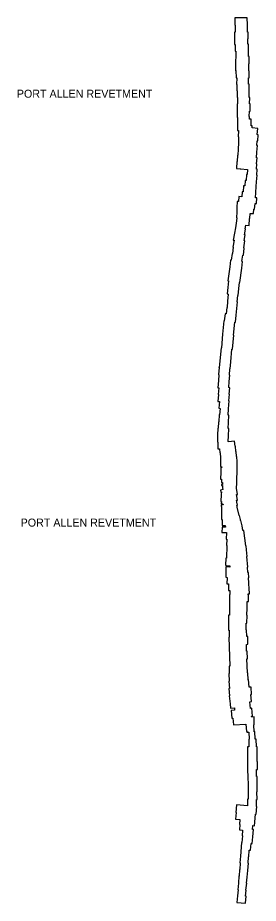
# Model space of a CAD drawing. Extents: x 2650582 to 3923188, y 277893 to 989177.
# Drawn here: x 3318306 to 3323118, y 703862 to 721562 of the extents above; entities that cross this region are included whole.
import ezdxf

# ---------------------------------------------------------------- set-up
doc = ezdxf.new("R2010")
doc.units = 0
doc.layers.add('Level 3', color=7, linetype='Continuous')

msp = doc.modelspace()

# ---------------------------------------------------------------- linework, layer by layer
at = {"layer": 'Level 3'}
for points in [[(3322897, 721562), (3322648, 721559), (3322650, 721411), (3322654, 721411), (3322653, 721273), (3322644, 721273), (3322644, 721170)], [(3322907, 721142), (3322916, 721141), (3322917, 721271), (3322901, 721271), (3322902, 721421), (3322899, 721421), (3322897, 721562)], [(3322644, 721170), (3322643, 721170), (3322643, 721027), (3322654, 721027), (3322655, 720895), (3322671, 720894), (3322672, 720789), (3322667, 720790), (3322665, 720691), (3322664, 720647), (3322663, 720647), (3322663, 720503), (3322672, 720504), (3322674, 720363), (3322686, 720363), (3322685, 720230), (3322692, 720230)], [(3322938, 720237), (3322923, 720237), (3322924, 720363), (3322937, 720363), (3322936, 720501), (3322932, 720501), (3322932, 720639), (3322935, 720639), (3322937, 720784), (3322923, 720784), (3322923, 720904), (3322920, 720904), (3322920, 721033), (3322906, 721033), (3322907, 721142)], [(3322692, 720230), (3322691, 720100), (3322696, 720100), (3322696, 719970), (3322700, 719970), (3322699, 719840), (3322693, 719840), (3322693, 719698), (3322696, 719698), (3322695, 719567), (3322699, 719567), (3322699, 719438), (3322700, 719438), (3322703, 719305), (3322719, 719305), (3322718, 719181), (3322724, 719181), (3322721, 719060), (3322713, 718938), (3322718, 718938), (3322709, 718817), (3322704, 718817), (3322695, 718688), (3322691, 718688), (3322681, 718545), (3322753, 718540), (3322753, 718539), (3322770, 718539), (3322895, 718530)], [(3322993, 719358), (3322995, 719400), (3322974, 719401), (3322978, 719532), (3322943, 719533), (3322943, 719587), (3322938, 719587), (3322939, 719697), (3322958, 719697), (3322958, 719840), (3322945, 719840), (3322946, 719970), (3322938, 719970), (3322938, 720101), (3322936, 720101), (3322938, 720237)], [(3322954, 717651), (3323024, 717646), (3323031, 717736), (3323045, 717735), (3323053, 717849), (3323079, 717847), (3323087, 717963), (3323063, 717964), (3323070, 718066), (3323069, 718066), (3323077, 718187), (3323073, 718188), (3323080, 718283), (3323084, 718283), (3323093, 718415), (3323087, 718415), (3323095, 718532), (3323081, 718533), (3323088, 718640), (3323085, 718640), (3323094, 718762), (3323081, 718763), (3323088, 718874), (3323090, 718874), (3323099, 719005), (3323092, 719006), (3323098, 719101), (3323109, 719100), (3323118, 719224), (3323098, 719225), (3323109, 719347), (3322993, 719358)], [(3322895, 718530), (3322895, 718529), (3322904, 718529), (3322897, 718428), (3322883, 718429), (3322874, 718308), (3322857, 718309), (3322850, 718203), (3322824, 718205), (3322815, 718084), (3322798, 718085), (3322790, 717983), (3322732, 717987), (3322725, 717889)], [(3322725, 717889), (3322698, 717891), (3322690, 717772), (3322692, 717771), (3322686, 717675), (3322690, 717675), (3322682, 717566), (3322690, 717565), (3322685, 717502)], [(3322855, 717221), (3322842, 717223), (3322860, 717339), (3322854, 717340), (3322868, 717416), (3322933, 717411), (3322943, 717547), (3322946, 717546), (3322954, 717651)], [(3322685, 717502), (3322659, 717364), (3322661, 717363), (3322645, 717258), (3322640, 717259), (3322615, 717118)], [(3322546, 714167), (3322526, 714168), (3322537, 714292), (3322538, 714292), (3322549, 714415), (3322540, 714416), (3322552, 714547), (3322557, 714547), (3322568, 714685), (3322566, 714685), (3322592, 714939), (3322603, 714938), (3322630, 715217), (3322624, 715217), (3322652, 715475), (3322659, 715474), (3322678, 715618), (3322676, 715618), (3322691, 715750), (3322686, 715751), (3322700, 715882), (3322696, 715883), (3322711, 716013), (3322715, 716013), (3322731, 716150), (3322730, 716150), (3322743, 716272), (3322750, 716272), (3322789, 716553), (3322788, 716553), (3322803, 716691), (3322791, 716693), (3322808, 716819), (3322819, 716818), (3322837, 716959), (3322826, 716961), (3322852, 717103), (3322835, 717106), (3322855, 717221)], [(3322615, 717118), (3322633, 717115), (3322608, 716979), (3322616, 716978), (3322600, 716851), (3322593, 716852), (3322574, 716717), (3322565, 716718), (3322551, 716585), (3322547, 716585), (3322508, 716305), (3322519, 716303), (3322506, 716173), (3322510, 716173), (3322494, 716040), (3322515, 716038), (3322499, 715894), (3322505, 715894), (3322493, 715773), (3322491, 715773), (3322476, 715642), (3322456, 715644), (3322438, 715506), (3322430, 715506), (3322401, 715235), (3322405, 715235), (3322379, 714962), (3322378, 714962), (3322351, 714702), (3322348, 714702), (3322337, 714567), (3322335, 714568), (3322322, 714428), (3322329, 714427), (3322319, 714311), (3322324, 714310), (3322311, 714163)], [(3322311, 714163), (3322326, 714162), (3322314, 714028), (3322322, 714028), (3322310, 713893), (3322339, 713890), (3322326, 713757), (3322354, 713754), (3322345, 713628), (3322336, 713629), (3322327, 713483), (3322325, 713483), (3322318, 713359), (3322306, 713360), (3322300, 713216), (3322302, 713216), (3322300, 713082), (3322310, 713081), (3322309, 712946), (3322339, 712946)], [(3322642, 713100), (3322521, 713085), (3322521, 713091), (3322516, 713091), (3322519, 713208), (3322523, 713207), (3322529, 713351), (3322518, 713352), (3322524, 713471), (3322521, 713472), (3322530, 713617), (3322513, 713618), (3322522, 713748), (3322519, 713748), (3322534, 713903), (3322530, 713903), (3322542, 714039), (3322534, 714040), (3322546, 714167)], [(3322679, 712160), (3322684, 712160), (3322686, 712261), (3322691, 712261), (3322694, 712575), (3322697, 712575), (3322696, 712685), (3322693, 712685), (3322687, 712789), (3322682, 712789), (3322675, 712894), (3322668, 712893), (3322660, 712997), (3322656, 712996), (3322642, 713100)], [(3322339, 712946), (3322346, 712863), (3322353, 712863), (3322360, 712763), (3322360, 712763), (3322362, 712736), (3322361, 712700), (3322365, 712700), (3322363, 712594), (3322376, 712594), (3322376, 712586), (3322390, 712586), (3322390, 712571), (3322370, 712572), (3322368, 712482), (3322367, 712482), (3322365, 712342), (3322381, 712341), (3322380, 712271), (3322401, 712271), (3322400, 712265), (3322403, 712265), (3322402, 712231), (3322379, 712231), (3322379, 712211), (3322402, 712211), (3322401, 712164), (3322405, 712164), (3322408, 712132)], [(3322408, 712132), (3322362, 712120), (3322372, 712082), (3322379, 712084), (3322378, 712034), (3322375, 712034), (3322370, 711894), (3322379, 711894), (3322377, 711848), (3322412, 711847), (3322414, 711827), (3322376, 711828), (3322375, 711796), (3322383, 711795), (3322379, 711666), (3322385, 711665), (3322384, 711635), (3322383, 711635), (3322383, 711629), (3322380, 711535), (3322395, 711535), (3322398, 711516), (3322394, 711413), (3322456, 711411), (3322461, 711380), (3322396, 711383)], [(3322830, 711312), (3322811, 711310), (3322794, 711407), (3322793, 711407), (3322770, 711513), (3322763, 711511), (3322762, 711515), (3322763, 711532), (3322759, 711532), (3322743, 711614), (3322733, 711612), (3322697, 711782), (3322698, 711794), (3322694, 711795), (3322690, 711817), (3322702, 711819), (3322690, 711882), (3322691, 711893), (3322688, 711893), (3322684, 711917), (3322705, 711921), (3322683, 712032), (3322701, 712035), (3322679, 712160)], [(3322396, 711383), (3322392, 711275), (3322481, 711272)], [(3322481, 711272), (3322476, 711142), (3322486, 711141), (3322481, 711012), (3322489, 711011), (3322480, 710761), (3322470, 710762), (3322465, 710622), (3322470, 710622), (3322470, 710612), (3322549, 710609), (3322550, 710581), (3322469, 710584), (3322466, 710492), (3322471, 710492), (3322467, 710378), (3322494, 710377), (3322490, 710247), (3322522, 710246)], [(3322916, 710047), (3322939, 710049), (3322933, 710163), (3322936, 710163), (3322929, 710240), (3322929, 710255), (3322928, 710255), (3322927, 710264), (3322929, 710264), (3322922, 710367), (3322928, 710368), (3322920, 710471), (3322912, 710471), (3322902, 710579), (3322909, 710580), (3322891, 710793), (3322894, 710793), (3322883, 710928), (3322883, 710928), (3322877, 711008), (3322869, 711007), (3322830, 711312)], [(3322522, 710246), (3322520, 710113), (3322548, 710113), (3322548, 710031), (3322540, 710031), (3322539, 709624), (3322522, 709623), (3322523, 709320), (3322534, 709320), (3322537, 709183), (3322526, 709183), (3322547, 708600), (3322533, 708599), (3322538, 708454), (3322529, 708453), (3322536, 708301)], [(3322925, 708332), (3322915, 708331), (3322909, 708469), (3322899, 708469), (3322886, 708747), (3322902, 708748), (3322896, 708901), (3322883, 708901), (3322880, 709037), (3322912, 709039), (3322907, 709196), (3322887, 709195), (3322884, 709330), (3322877, 709331), (3322878, 709463), (3322892, 709463), (3322894, 709620), (3322892, 709620), (3322893, 709761), (3322895, 709761), (3322896, 709894), (3322920, 709893), (3322920, 710030), (3322916, 710030), (3322916, 710047)], [(3322536, 708301), (3322532, 708300), (3322544, 708154), (3322532, 708153), (3322541, 708010), (3322538, 708009), (3322554, 707851), (3322557, 707851), (3322565, 707760), (3322639, 707767), (3322644, 707722), (3322574, 707715), (3322590, 707559), (3322610, 707562), (3322619, 707426), (3322866, 707443), (3322881, 707299), (3322889, 707300)], [(3323035, 707586), (3322986, 707585), (3322985, 707602), (3323005, 707604), (3322989, 707759), (3322965, 707756), (3322950, 707889), (3322980, 707892), (3322967, 708034), (3322985, 708036), (3322975, 708184), (3322938, 708181), (3322925, 708332)], [(3323002, 705335), (3323010, 705414), (3323040, 705412), (3323060, 705644), (3323076, 705643), (3323090, 705796), (3323083, 705796), (3323080, 705938), (3323094, 705938), (3323091, 706093), (3323096, 706093), (3323093, 706241), (3323098, 706242), (3323093, 706394), (3323083, 706394), (3323080, 706537), (3323104, 706538), (3323100, 706694), (3323098, 706694), (3323094, 706992), (3323079, 706991), (3323077, 707143), (3323053, 707143), (3323049, 707293), (3323033, 707292), (3323029, 707432), (3323038, 707433), (3323035, 707586)], [(3322889, 707300), (3322889, 707282), (3322930, 707283), (3322934, 707142), (3322929, 707141), (3322931, 706989), (3322899, 706989), (3322903, 706693), (3322899, 706693), (3322903, 706533), (3322904, 706533), (3322907, 706385), (3322910, 706385), (3322915, 706239), (3322914, 706239), (3322917, 706100), (3322915, 706100), (3322918, 705944), (3322900, 705944), (3322903, 705812), (3322679, 705832), (3322666, 705680), (3322673, 705679), (3322661, 705542), (3322751, 705534), (3322743, 705439), (3322751, 705438), (3322741, 705330)], [(3322692, 703876), (3322861, 703862), (3322873, 704003), (3322865, 704003), (3322876, 704127), (3322872, 704127), (3322886, 704263), (3322884, 704263), (3322894, 704387), (3322895, 704387), (3322906, 704520), (3322909, 704519), (3322920, 704664), (3322914, 704664), (3322924, 704790), (3322926, 704790), (3322938, 704927), (3322963, 704925), (3322974, 705058), (3322998, 705056), (3323011, 705193), (3323007, 705193), (3323020, 705334), (3323002, 705335)], [(3322741, 705330), (3322804, 705324), (3322794, 705212), (3322800, 705211), (3322787, 705080), (3322785, 705080), (3322760, 704805), (3322763, 704805), (3322752, 704671), (3322757, 704670), (3322746, 704535), (3322743, 704535), (3322733, 704407), (3322730, 704408), (3322719, 704267), (3322725, 704267), (3322711, 704134), (3322715, 704134), (3322703, 704010), (3322692, 703876)]]:
    msp.add_lwpolyline(points, dxfattribs=at)

# ---------------------------------------------------------------- texts
for p in [(3318289, 719963), (3318365, 711391)]:
    msp.add_text('PORT ALLEN REVETMENT', height=160, dxfattribs=at).set_placement(p)

doc.saveas('drawing.dxf')
